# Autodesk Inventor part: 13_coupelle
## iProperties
Created: 2002-11
Part Number: 13_coupelle
Material: Cuivre
Document SubType Name: Modélisation
Designer: FIEVET
Control State: 0
Master: False
Checked Out: False
Shininess: 71.0
Length Units: 11269
Angle Units: 11279
Time Units: 11290
Mass Units: 11283
Length Display Precision: 3
Angle Display Precision: 2
Compacted: True
Density: 8.94
Volumn: 0.36894158825069645
Area: 4.5077800926871125
PropertySet Name: Model Information
Author: FIEVET
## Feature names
1. Révolution1 [Revolution]
